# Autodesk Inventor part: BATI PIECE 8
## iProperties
Created: 2004-11
Part Number: BATI PIECE 8
Document SubType Name: Modeling
Designer: Bruno
Manufacturer: Standard
Standards Organization: Custom
Author: Bruno
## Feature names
1. Base1
2. Chanfrein1 [Chamfer]
